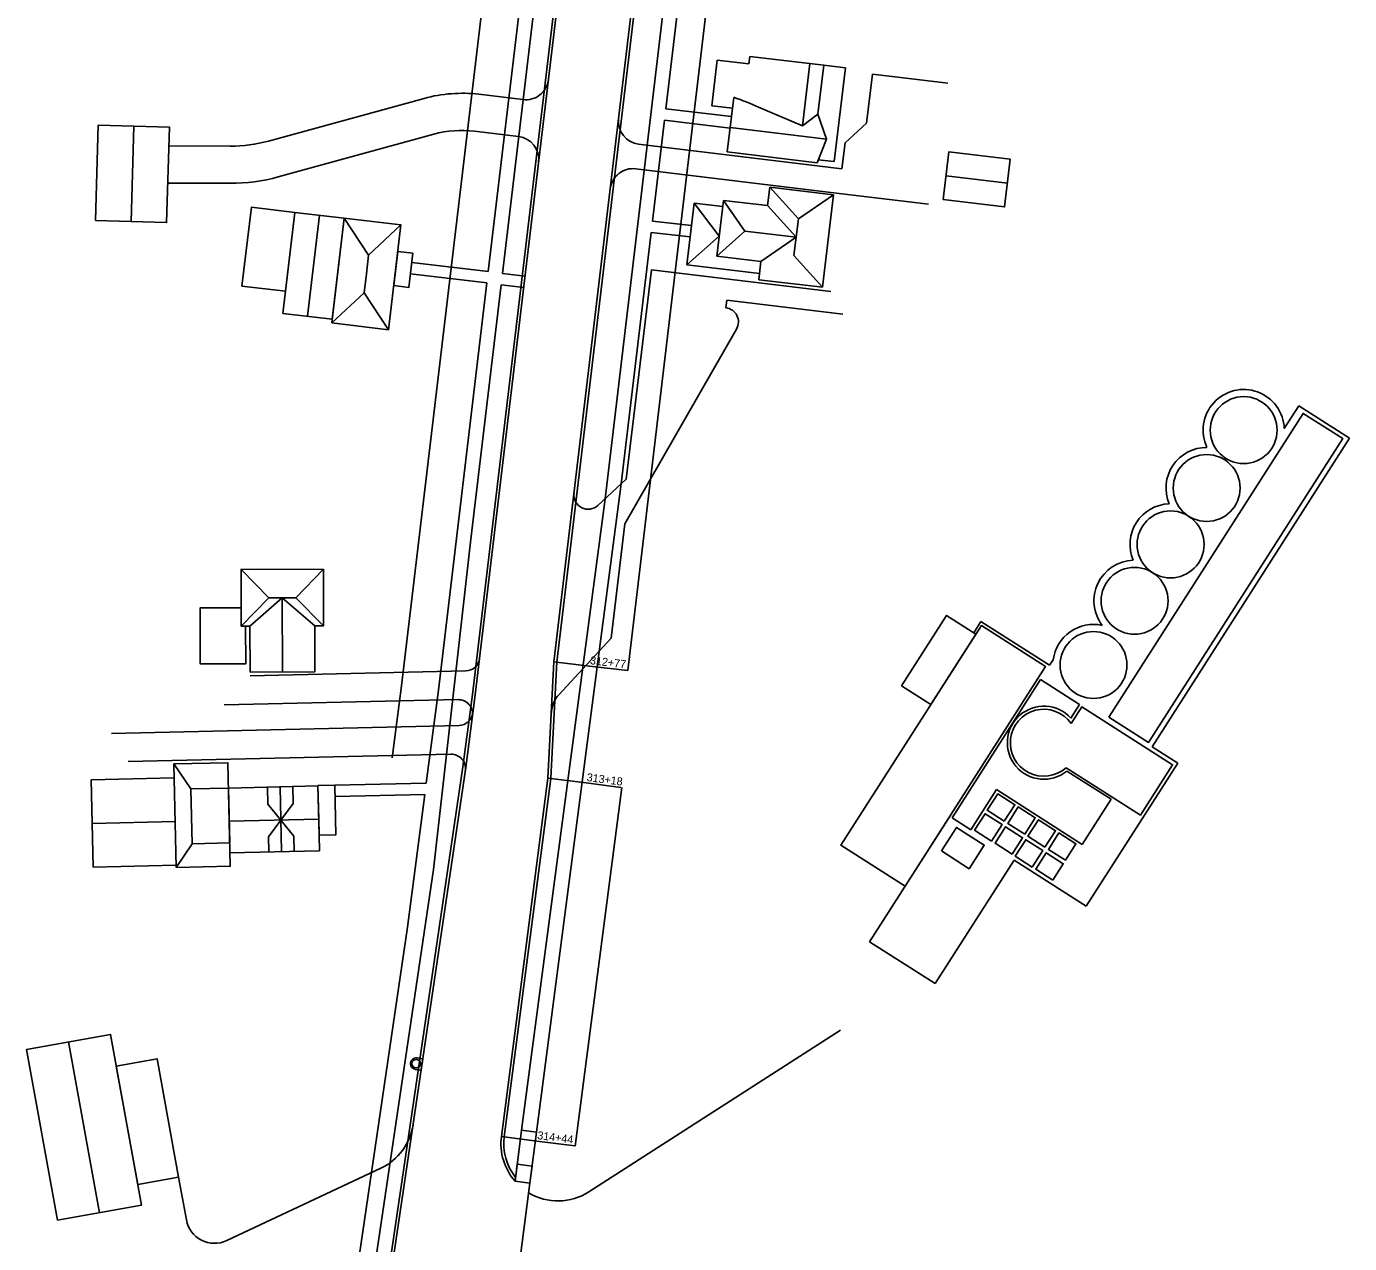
# Model space of a CAD drawing. Extents: x 107766 to 4387554, y 20109 to 1193017.
# Drawn here: x 1746495.9 to 1746958.9, y 279463 to 279889 of the extents above; entities that cross this region are included whole.
import ezdxf

# ---------------------------------------------------------------- set-up
doc = ezdxf.new("R2010")
doc.units = 0
for name, color, linetype in [('GM_X_State_Route', 7, 'Continuous'), ('GM_X_US_Route', 7, 'Continuous'), ('GM_X_US_Shield', 7, 'Continuous'), ('Level 60', 7, 'Continuous'), ('SC_Scratch1', 7, 'Continuous'), ('SC_Scratch10', 7, 'Continuous'), ('SC_Scratch5', 7, 'Continuous'), ('SC_Scratch8', 7, 'Continuous')]:
    doc.layers.add(name, color=color, linetype=linetype)

msp = doc.modelspace()

# ---------------------------------------------------------------- linework, layer by layer
at = {"layer": 'GM_X_State_Route'}
for p, q in [((1746632.57, 279528), (1746634.56, 279527.7)), ((1746634.56, 279527.7), (1746633.97, 279523.71)), ((1746633.97, 279523.71), (1746631.98, 279524))]:
    msp.add_line(p, q, dxfattribs=at)
msp.add_circle((1746632.27, 279526), 1.5, dxfattribs=at)
msp.add_arc((1746632.27, 279526), 2.02, 81.6112, 261.6112, dxfattribs=at)
at = {"layer": 'GM_X_US_Route'}
for p, q in [((1746669.14, 279502.7), (1746666.82, 279484.85)), ((1746669.1, 279502.7), (1746674.35, 279502.02)), ((1746672.03, 279484.17), (1746674.35, 279502.02)), ((1746667.55, 279490.8), (1746672.81, 279490.12))]:
    msp.add_line(p, q, dxfattribs=at)
msp.add_lwpolyline([(1746667.59, 279490.8), (1746666.82, 279484.85), (1746672.03, 279484.17), (1746672.81, 279490.12), (1746667.59, 279490.8)], dxfattribs=at)
at = {"layer": 'GM_X_US_Shield'}
for p, q in [((1746765.15, 280158.41), (1746706.28, 279663.55)), ((1746765.15, 280158.41), (1746706.28, 279663.55)), ((1746704.15, 279622.61), (1746687.84, 279497.18))]:
    msp.add_line(p, q, dxfattribs=at)
msp.add_lwpolyline([(1746757.71, 280767.32), (1746687.69, 280167.57), (1746627.1, 279658.26), (1746623.82, 279633.05)], dxfattribs=at)
at = {"layer": 'Level 60'}
for p, q in [((1746789.87, 279855.18), (1746791.93, 279872.28)), ((1746791.93, 279872.28), (1746818.24, 279869.1)), ((1746669.61, 279863.38), (1746654.21, 279865.24)), ((1746634.98, 279863.82), (1746580.54, 279848.87)), ((1746782.31, 279848.25), (1746789.87, 279855.18)), ((1746638.42, 279851.28), (1746583.99, 279836.34)), ((1746668.1, 279850.47), (1746652.65, 279852.33)), ((1746567.16, 279847.09), (1746545.7, 279847.16)), ((1746781.22, 279839.22), (1746710.06, 279847.81)), ((1746781.22, 279839.22), (1746782.31, 279848.25)), ((1746780.3, 279830.57), (1746709.06, 279839.17)), ((1746567.12, 279834.09), (1746545.32, 279834.16)), ((1746780.3, 279830.57), (1746811.47, 279826.81)), ((1746705.7, 279730.56), (1746714.53, 279803.76)), ((1746777.3, 279796.19), (1746714.53, 279803.76)), ((1746740.6, 279790.55), (1746740.92, 279793.23)), ((1746740.92, 279793.23), (1746781.54, 279788.33)), ((1746705.3, 279714.94), (1746744.33, 279783.1)), ((1746695.86, 279721.37), (1746705.7, 279730.56)), ((1746700.46, 279674.87), (1746705.3, 279714.94)), ((1746682.19, 279655.13), (1746700.46, 279674.87)), ((1746574.12, 279661.74), (1746649.57, 279663.46)), ((1746564.99, 279651.53), (1746646.88, 279653.39)), ((1746525.58, 279641.6), (1746647.23, 279644.36)), ((1746531.47, 279631.73), (1746644.38, 279634.29)), ((1746692.71, 279481.13), (1746780.67, 279537.7)), ((1746619.88, 279489.44), (1746565.92, 279464.08)), ((1746549.12, 279486.26), (1746551.83, 279471.34))]:
    msp.add_line(p, q, dxfattribs=at)
for centre, radius, start, end in [((1746670.57, 279871.32), 8, 263.1172, 353.2157), ((1746648.22, 279815.6), 50, 83.1172, 105.348), ((1746711.02, 279855.75), 8, 173.2157, 263.1172), ((1746648.22, 279815.6), 37, 83.1172, 105.348), ((1746667.15, 279842.52), 8, 353.2157, 83.1172), ((1746567.31, 279897.09), 50, 269.8271, 285.348), ((1746567.31, 279897.09), 63, 269.8271, 285.348), ((1746708.1, 279831.23), 8, 83.1172, 173.2157), ((1746740, 279785.58), 5, 330.2003, 83.1172), ((1746692.44, 279725.02), 5, 173.2157, 313.0475), ((1746649.46, 279668.45), 5, 271.3, 353.2157), ((1746646.99, 279648.39), 5, 352.5947, 91.3), ((1746689.53, 279648.33), 10, 137.2095, 177.0482), ((1746647.12, 279649.36), 5, 271.3, 352.5947), ((1746644.49, 279629.29), 5, 351.6112, 91.3), ((1746611.37, 279507.54), 20, 295.1688, 351.6112), ((1746681.89, 279497.95), 20, 239.0166, 302.7473), ((1746561.67, 279473.13), 10, 190.3194, 295.1688)]:
    msp.add_arc(centre, radius, start, end, dxfattribs=at)
at = {"layer": 'SC_Scratch1'}
for p, q in [((1746742.56, 279857.42), (1746719.6, 279860.15)), ((1746742.09, 279853.45), (1746719.12, 279856.18)), ((1746728.6, 279819.28), (1746714.93, 279820.9)), ((1746728.13, 279815.31), (1746714.45, 279816.93)), ((1746630.73, 279806.36), (1746657.43, 279803.18)), ((1746630.26, 279802.39), (1746656.96, 279799.21)), ((1746662.4, 279802.59), (1746670.34, 279801.65)), ((1746661.92, 279798.62), (1746669.87, 279797.67)), ((1746696.22, 279670.29), (1746703.99, 279728.97)), ((1746669.14, 279502.7), (1746698.32, 279723.68)), ((1746638.26, 279593.91), (1746651.33, 279709.61)), ((1746674.35, 279502.02), (1746696.22, 279670.29)), ((1746603.74, 279623.45), (1746635.78, 279624.18)), ((1746603.83, 279619.45), (1746635.26, 279620.16)), ((1746638.26, 279593.91), (1746618.17, 279457.66)), ((1746629.22, 279573.71), (1746612.23, 279458.54))]:
    msp.add_line(p, q, dxfattribs=at)
for points in [[(1746757.86, 280613.33), (1746705.56, 280165.46), (1746662.4, 279802.59)], [(1746749.04, 280149.97), (1746698.32, 279723.68)], [(1746674.55, 279947.09), (1746657.43, 279803.18)], [(1746727.29, 279924.86), (1746719.6, 279860.15)], [(1746719.12, 279856.18), (1746714.93, 279820.9)], [(1746714.45, 279816.93), (1746703.99, 279728.97)], [(1746656.96, 279799.21), (1746640, 279656.66), (1746635.78, 279624.18)], [(1746661.92, 279798.62), (1746651.33, 279709.61)], [(1746635.26, 279620.16), (1746629.22, 279573.71)]]:
    msp.add_lwpolyline(points, dxfattribs=at)
at = {"layer": 'SC_Scratch10'}
for p, q in [((1746680.46, 279666.62), (1746678.36, 279625.96)), ((1746706.28, 279663.55), (1746692.88, 279665.14)), ((1746649.6, 279629.7), (1746624.11, 279456.79)), ((1746703.87, 279622.64), (1746691.7, 279624.23)), ((1746687.73, 279497.19), (1746674.42, 279498.92)), ((1746666.82, 279484.85), (1746672.03, 279484.17)), ((1746659.63, 279388.7), (1746672.03, 279484.17))]:
    msp.add_line(p, q, dxfattribs=at)
for points in [[(1746875.06, 281929.89), (1746898.53, 281748.19), (1746905.88, 281680.52), (1746907.07, 281648.82), (1746906.91, 281621.12), (1746904.04, 281580.18), (1746896.74, 281504.9), (1746809.36, 280761.28), (1746739.33, 280161.48), (1746680.46, 279666.62)], [(1746871.33, 281512.26), (1746870.88, 281507.67), (1746783.54, 280764.31), (1746713.51, 280164.53), (1746652.9, 279655.05), (1746649.6, 279629.7)], [(1746692.88, 279665.14), (1746680.46, 279666.62)], [(1746678.36, 279625.96), (1746662.06, 279500.53)], [(1746691.7, 279624.23), (1746678.36, 279625.96)], [(1746674.42, 279498.92), (1746662.06, 279500.53)]]:
    msp.add_lwpolyline(points, dxfattribs=at)
msp.add_arc((1746681.92, 279497.99), 20.02, 172.7142, 221.0326, dxfattribs=at)
at = {"layer": 'SC_Scratch5'}
for p, q in [((1746681.46, 279666.57), (1746679.36, 279625.91)), ((1746648.61, 279629.84), (1746623.12, 279456.93))]:
    msp.add_line(p, q, dxfattribs=at)
for points in [[(1746870.57, 281514.85), (1746869.89, 281507.78), (1746782.54, 280764.42), (1746712.52, 280164.64), (1746651.91, 279655.18), (1746648.61, 279629.83)], [(1746737.92, 280141.18), (1746681.45, 279666.5)], [(1746679.35, 279625.83), (1746663.05, 279500.4)]]:
    msp.add_lwpolyline(points, dxfattribs=at)
msp.add_arc((1746681.92, 279497.99), 19.02, 172.7142, 218.3028, dxfattribs=at)
at = {"layer": 'SC_Scratch8'}
for p, q in [((1746748.99, 279878.49), (1746748.68, 279875.86)), ((1746774.84, 279875.42), (1746748.99, 279878.49)), ((1746737.54, 279877.19), (1746735.64, 279861.25)), ((1746748.68, 279875.86), (1746737.54, 279877.19)), ((1746770.04, 279875.99), (1746767.44, 279854.17)), ((1746772.79, 279858.24), (1746774.84, 279875.42)), ((1746774.84, 279875.42), (1746782.42, 279874.52)), ((1746782.42, 279874.52), (1746778.52, 279841.71)), ((1746743.37, 279864.18), (1746741.09, 279845.06)), ((1746735.64, 279861.25), (1746742.91, 279860.38)), ((1746767.44, 279854.17), (1746752.06, 279860.71)), ((1746767.44, 279854.17), (1746772.79, 279858.24)), ((1746775.84, 279849.56), (1746772.79, 279858.24)), ((1746532.47, 279820.73), (1746533.44, 279854.09)), ((1746775.84, 279849.56), (1746742.1, 279853.57)), ((1746772.51, 279841.32), (1746775.84, 279849.56)), ((1746741.09, 279845.06), (1746772.51, 279841.32)), ((1746778.52, 279841.71), (1746772.93, 279842.37)), ((1746839.15, 279834.18), (1746817.64, 279836.74)), ((1746755.22, 279826.29), (1746755.98, 279832.7)), ((1746765.97, 279821.62), (1746755.98, 279832.7)), ((1746755.98, 279832.7), (1746778.28, 279830.05)), ((1746729.54, 279827.17), (1746726.96, 279805.54)), ((1746739.49, 279825.99), (1746729.54, 279827.17)), ((1746738.25, 279815.59), (1746729.54, 279827.17)), ((1746739.74, 279828.13), (1746737.42, 279808.61)), ((1746755.22, 279826.29), (1746739.74, 279828.13)), ((1746747.23, 279817.34), (1746739.74, 279828.13)), ((1746765.97, 279821.62), (1746778.28, 279830.05)), ((1746778.28, 279830.05), (1746774.43, 279797.71)), ((1746594.22, 279787.56), (1746598.42, 279822.91)), ((1746765.21, 279815.2), (1746755.22, 279826.29)), ((1746615.59, 279808.99), (1746607.04, 279821.88)), ((1746615.59, 279808.99), (1746626.92, 279819.51)), ((1746764.44, 279808.79), (1746765.97, 279821.62)), ((1746738.25, 279815.59), (1746726.96, 279805.54)), ((1746747.23, 279817.34), (1746737.42, 279808.61)), ((1746765.21, 279815.2), (1746747.23, 279817.34)), ((1746765.21, 279815.2), (1746752.89, 279806.77)), ((1746614.8, 279802.36), (1746615.59, 279808.99)), ((1746752.89, 279806.77), (1746737.42, 279808.61)), ((1746764.44, 279808.79), (1746774.43, 279797.71)), ((1746726.96, 279805.54), (1746752.39, 279802.51)), ((1746752.13, 279800.36), (1746752.89, 279806.77)), ((1746614.01, 279795.73), (1746614.8, 279802.36)), ((1746774.43, 279797.71), (1746752.13, 279800.36)), ((1746614.01, 279795.73), (1746602.67, 279785.21)), ((1746614.01, 279795.73), (1746622.56, 279782.84)), ((1746941.09, 279756.22), (1746936.01, 279748.28)), ((1746958.85, 279744.87), (1746941.09, 279756.22)), ((1746889.83, 279636.87), (1746958.85, 279744.87)), ((1746580.7, 279689.05), (1746570.98, 279698.95)), ((1746590.09, 279689.07), (1746599.76, 279699.02)), ((1746580.7, 279689.05), (1746571.02, 279679.11)), ((1746574.05, 279679.12), (1746585.39, 279689.06)), ((1746585.39, 279689.06), (1746580.7, 279689.05)), ((1746590.09, 279689.07), (1746585.39, 279689.06)), ((1746596.77, 279679.17), (1746585.39, 279689.06)), ((1746585.39, 279689.06), (1746585.45, 279663.09)), ((1746590.09, 279689.07), (1746599.8, 279679.17)), ((1746574.09, 279663.06), (1746574.05, 279679.12)), ((1746596.81, 279663.11), (1746596.77, 279679.17)), ((1746829.87, 279680.77), (1746827.33, 279676.79)), ((1746853.9, 279665.41), (1746829.87, 279680.77)), ((1746853.9, 279665.41), (1746855.17, 279667.38)), ((1746574.09, 279663.06), (1746596.81, 279663.11)), ((1746850.71, 279660.41), (1746819.79, 279612.03)), ((1746864.37, 279651.68), (1746850.71, 279660.41)), ((1746861.33, 279646.92), (1746864.37, 279651.68)), ((1746898.74, 279631.17), (1746889.83, 279636.87)), ((1746553.42, 279622.17), (1746547.48, 279630.9)), ((1746875.38, 279618.53), (1746859.94, 279628.4)), ((1746898.74, 279631.17), (1746866.74, 279581.1)), ((1746518.56, 279625.32), (1746547.59, 279625.98)), ((1746518.9, 279610.07), (1746518.56, 279625.32)), ((1746597.88, 279623.18), (1746566.55, 279622.47)), ((1746580.3, 279616.87), (1746580.16, 279622.78)), ((1746584.59, 279622.88), (1746585.1, 279600.24)), ((1746589.15, 279617.08), (1746589.02, 279622.98)), ((1746598.14, 279611.54), (1746597.88, 279623.18)), ((1746826.35, 279607.84), (1746835.33, 279621.89)), ((1746835.33, 279621.89), (1746865.29, 279602.74)), ((1746584.85, 279611.23), (1746580.3, 279616.87)), ((1746584.85, 279611.23), (1746589.15, 279617.08)), ((1746865.29, 279602.74), (1746875.38, 279618.53)), ((1746547.94, 279610.72), (1746518.9, 279610.07)), ((1746518.9, 279610.07), (1746519.25, 279594.81)), ((1746566.81, 279610.82), (1746598.14, 279611.54)), ((1746584.85, 279611.23), (1746580.56, 279605.39)), ((1746584.85, 279611.23), (1746589.41, 279605.59)), ((1746598.14, 279611.54), (1746598.39, 279600.54)), ((1746790.92, 279568.69), (1746819.28, 279613.06)), ((1746819.79, 279612.03), (1746826.35, 279607.84)), ((1746580.56, 279605.39), (1746580.68, 279600.14)), ((1746589.41, 279605.59), (1746589.53, 279600.34)), ((1746553.86, 279602.98), (1746548.3, 279594.65)), ((1746598.39, 279600.54), (1746567.06, 279599.83)), ((1746519.25, 279594.81), (1746548.28, 279595.47)), ((1746813.86, 279554.02), (1746841.48, 279597.24)), ((1746841.48, 279597.24), (1746866.74, 279581.1)), ((1746790.92, 279568.69), (1746813.86, 279554.02)), ((1746510.57, 279533.58), (1746521.44, 279473.85))]:
    msp.add_line(p, q, dxfattribs=at)
for points in [[(1746520.01, 279821.09), (1746520.98, 279854.45), (1746545.89, 279853.73), (1746544.92, 279820.37)], [(1746816.64, 279828.38), (1746818.63, 279845.1), (1746840.14, 279842.54), (1746838.15, 279825.82)], [(1746589.81, 279823.93), (1746586.52, 279796.31), (1746571.28, 279798.13), (1746574.56, 279825.74)], [(1746607.04, 279821.88), (1746602.83, 279786.53), (1746585.6, 279788.58), (1746589.81, 279823.93)], [(1746602.67, 279785.21), (1746607.04, 279821.88), (1746626.92, 279819.51), (1746622.56, 279782.84)], [(1746624.4, 279798.31), (1746625.82, 279810.24), (1746631.12, 279809.6), (1746629.7, 279797.67)], [(1746874.66, 279647.26), (1746942.61, 279753.59), (1746956.48, 279744.73), (1746888.52, 279638.4)], [(1746803.32, 279588.08), (1746852.47, 279664.99), (1746830.05, 279679.32), (1746780.89, 279602.41)], [(1746812.37, 279651.66), (1746828.11, 279676.29), (1746817.82, 279682.87), (1746802.08, 279658.24)], [(1746548.3, 279594.65), (1746547.48, 279630.9), (1746566.34, 279631.33), (1746567.17, 279595.08)], [(1746598.27, 279606), (1746597.88, 279623.32), (1746603.74, 279623.45), (1746604.13, 279606.13)], [(1746566.98, 279603.28), (1746566.55, 279622.47), (1746553.42, 279622.17), (1746553.86, 279602.98)], [(1746838.05, 279610.87), (1746841.73, 279616.62), (1746835.77, 279620.43), (1746832.09, 279614.68)], [(1746845.22, 279606.29), (1746848.89, 279612.04), (1746842.94, 279615.85), (1746839.26, 279610.1)], [(1746833.6, 279603.91), (1746837.28, 279609.66), (1746831.32, 279613.47), (1746827.64, 279607.71)], [(1746852.28, 279601.78), (1746855.96, 279607.53), (1746850, 279611.33), (1746846.33, 279605.58)], [(1746816.02, 279600.43), (1746821.31, 279608.7), (1746831, 279602.51), (1746825.71, 279594.24)], [(1746840.76, 279599.33), (1746844.44, 279605.08), (1746838.49, 279608.89), (1746834.81, 279603.13)], [(1746859.45, 279597.2), (1746863.12, 279602.95), (1746857.17, 279606.75), (1746853.49, 279601)], [(1746847.83, 279594.81), (1746851.51, 279600.56), (1746845.55, 279604.37), (1746841.87, 279598.62)], [(1746855, 279590.23), (1746858.67, 279595.98), (1746852.72, 279599.79), (1746849.04, 279594.04)], [(1746506.74, 279471.18), (1746495.86, 279530.9), (1746525.28, 279536.26), (1746536.15, 279476.53)], [(1746534.85, 279483.66), (1746527.31, 279525.11), (1746541.57, 279527.71), (1746549.12, 279486.26)]]:
    msp.add_lwpolyline(points, close=True, dxfattribs=at)
for points in [[(1746574.05, 279679.12), (1746571.02, 279679.11), (1746570.98, 279698.95), (1746599.76, 279699.02), (1746599.8, 279679.17), (1746596.77, 279679.17)], [(1746571.01, 279685.52), (1746556.64, 279685.49), (1746556.69, 279665.92), (1746572.57, 279665.96), (1746572.54, 279679.13)], [(1746861.45, 279645.06), (1746865.16, 279650.87), (1746896.9, 279630.58), (1746885.65, 279612.97), (1746859.68, 279629.57)]]:
    msp.add_lwpolyline(points, dxfattribs=at)
for centre in [(1746921.81, 279747.73), (1746908.85, 279727.46), (1746896.24, 279707.72), (1746883.62, 279687.98), (1746869.26, 279665.51)]:
    msp.add_circle(centre, 11.71, dxfattribs=at)
for centre, radius, start, end in [((1746719.9, 279792.95), 75, 64.6151, 71.7695), ((1746921.81, 279747.73), 14.21, 2.1999, 205.2373), ((1746908.85, 279727.46), 14.21, 89.5948, 202.9151), ((1746896.24, 279707.72), 14.21, 91.917, 202.9151), ((1746883.62, 279687.98), 14.21, 91.917, 217.1195), ((1746869.26, 279665.51), 14.21, 77.7127, 172.4264), ((1746851.88, 279638.31), 12.78, 42.3103, 309.1359), ((1746851.88, 279638.31), 11.71, 35.1828, 311.7357)]:
    msp.add_arc(centre, radius, start, end, dxfattribs=at)

# ---------------------------------------------------------------- texts
at = {"layer": 'SC_Scratch10'}
for s, rotation, p in [('312+77', 353.2157, (1746692.98, 279665.83)), ('313+18', 352.5947, (1746691.8, 279624.92)), ('314+44', 352.5947, (1746674.52, 279499.62))]:
    msp.add_text(s, height=2.8, rotation=rotation, dxfattribs=at).set_placement(p)

doc.saveas('drawing.dxf')
